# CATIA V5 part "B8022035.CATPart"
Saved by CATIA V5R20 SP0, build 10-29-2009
Part number: B8022035
Revision: 5
Definition: design
Nomenclature: B8022035
Source: made
Description: NOT SPECIFIED
Bounding box of the stored display mesh (mm): x -18 to 18, y -18 to 18, z -9 to 35
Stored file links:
  C:\Users\Utente\Desktop\3D files B802\B8022035.CATPart
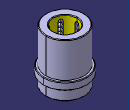
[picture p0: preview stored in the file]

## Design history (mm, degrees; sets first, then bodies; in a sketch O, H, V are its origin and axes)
Body1 "MANIFOLD_SOLID_BREP #38" (main body)
  Solid1: solid without history
Body2 "MANIFOLD_SOLID_BREP #76"
  Solid2: solid without history
Body3 "MANIFOLD_SOLID_BREP #114"
  Solid3: solid without history
Body4 "MANIFOLD_SOLID_BREP #152"
  Solid4: solid without history
Body5 "MANIFOLD_SOLID_BREP #190"
  Solid5: solid without history
Body6 "MANIFOLD_SOLID_BREP #228"
  Solid6: solid without history
Body7 "MANIFOLD_SOLID_BREP #266"
  Solid7: solid without history
Body8 "MANIFOLD_SOLID_BREP #304"
  Solid8: solid without history
Body9 "MANIFOLD_SOLID_BREP #2014"
  Solid9: solid without history
Body10 "MANIFOLD_SOLID_BREP #2052"
  Solid10: solid without history
Body11 "MANIFOLD_SOLID_BREP #2090"
  Solid11: solid without history
Body12 "MANIFOLD_SOLID_BREP #2128"
  Solid12: solid without history
Body13 "MANIFOLD_SOLID_BREP #2166"
  Solid13: solid without history
Body14 "MANIFOLD_SOLID_BREP #2204"
  Solid14: solid without history
Body15 "MANIFOLD_SOLID_BREP #2242"
  Solid15: solid without history
Body16 "MANIFOLD_SOLID_BREP #2280"
  Solid16: solid without history
Body17 "MANIFOLD_SOLID_BREP #2318"
  Solid17: solid without history
Body18 "MANIFOLD_SOLID_BREP #2356"
  Solid18: solid without history
Body19 "MANIFOLD_SOLID_BREP #2394"
  Solid19: solid without history
Body20 "MANIFOLD_SOLID_BREP #2432"
  Solid20: solid without history
Body21 "MANIFOLD_SOLID_BREP #2470"
  Solid21: solid without history
Body22 "MANIFOLD_SOLID_BREP #2508"
  Solid22: solid without history
Body23 "MANIFOLD_SOLID_BREP #2546"
  Solid23: solid without history
Body24 "MANIFOLD_SOLID_BREP #2584"
  Solid24: solid without history
Body25 "MANIFOLD_SOLID_BREP #2622"
  Solid25: solid without history
Body26 "MANIFOLD_SOLID_BREP #2660"
  Solid26: solid without history
Body27 "MANIFOLD_SOLID_BREP #2698"
  Solid27: solid without history
Body28 "MANIFOLD_SOLID_BREP #2736"
  Solid28: solid without history
Body29 "MANIFOLD_SOLID_BREP #2774"
  Solid29: solid without history
Body30 "MANIFOLD_SOLID_BREP #2812"
  Solid30: solid without history
Body31 "MANIFOLD_SOLID_BREP #2850"
  Solid31: solid without history
Body32 "MANIFOLD_SOLID_BREP #2888"
  Solid32: solid without history
Body33 "MANIFOLD_SOLID_BREP #2926"
  Solid33: solid without history
Body34 "MANIFOLD_SOLID_BREP #2964"
  Solid34: solid without history
Body35 "MANIFOLD_SOLID_BREP #3002"
  Solid35: solid without history
Body36 "MANIFOLD_SOLID_BREP #3040"
  Solid36: solid without history
Body37 "MANIFOLD_SOLID_BREP #3078"
  Solid37: solid without history
Body38 "MANIFOLD_SOLID_BREP #3116"
  Solid38: solid without history
Body39 "MANIFOLD_SOLID_BREP #3154"
  Solid39: solid without history
Body40 "MANIFOLD_SOLID_BREP #3192"
  Solid40: solid without history
Body41 "MANIFOLD_SOLID_BREP #3230"
  Solid41: solid without history
Body42 "MANIFOLD_SOLID_BREP #3268"
  Solid42: solid without history
Body43 "MANIFOLD_SOLID_BREP #3306"
  Solid43: solid without history
Body44 "MANIFOLD_SOLID_BREP #3344"
  Solid44: solid without history
Body45 "MANIFOLD_SOLID_BREP #3382"
  Solid45: solid without history
Body46 "MANIFOLD_SOLID_BREP #3420"
  Solid46: solid without history
Body47 "MANIFOLD_SOLID_BREP #3458"
  Solid47: solid without history
Body48 "MANIFOLD_SOLID_BREP #3496"
  Solid48: solid without history
Body49 "MANIFOLD_SOLID_BREP #3534"
  Solid49: solid without history
Body50 "MANIFOLD_SOLID_BREP #3572"
  Solid50: solid without history
Body51 "MANIFOLD_SOLID_BREP #3610"
  Solid51: solid without history
Body52 "MANIFOLD_SOLID_BREP #3648"
  Solid52: solid without history
Body53 "MANIFOLD_SOLID_BREP #3686"
  Solid53: solid without history
Body54 "MANIFOLD_SOLID_BREP #3724"
  Solid54: solid without history
Body55 "MANIFOLD_SOLID_BREP #3762"
  Solid55: solid without history
Body56 "MANIFOLD_SOLID_BREP #3800"
  Solid56: solid without history
Body57 "MANIFOLD_SOLID_BREP #3838"
  Solid57: solid without history
Body58 "MANIFOLD_SOLID_BREP #3876"
  Solid58: solid without history
Body59 "MANIFOLD_SOLID_BREP #3914"
  Solid59: solid without history
Body60 "MANIFOLD_SOLID_BREP #3952"
  Solid60: solid without history
Body61 "MANIFOLD_SOLID_BREP #3990"
  Solid61: solid without history
Body62 "MANIFOLD_SOLID_BREP #4028"
  Solid62: solid without history
Body63 "MANIFOLD_SOLID_BREP #4066"
  Solid63: solid without history
Body64 "MANIFOLD_SOLID_BREP #4104"
  Solid64: solid without history
Body65 "MANIFOLD_SOLID_BREP #4142"
  Solid65: solid without history
Body66 "MANIFOLD_SOLID_BREP #4180"
  Solid66: solid without history
Body67 "MANIFOLD_SOLID_BREP #4218"
  Solid67: solid without history
Body68 "MANIFOLD_SOLID_BREP #4256"
  Solid68: solid without history
Body69 "MANIFOLD_SOLID_BREP #4294"
  Solid69: solid without history
Body70 "MANIFOLD_SOLID_BREP #4332"
  Solid70: solid without history
Body71 "MANIFOLD_SOLID_BREP #4370"
  Solid71: solid without history
Body72 "MANIFOLD_SOLID_BREP #4408"
  Solid72: solid without history
Body73 "MANIFOLD_SOLID_BREP #4446"
  Solid73: solid without history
